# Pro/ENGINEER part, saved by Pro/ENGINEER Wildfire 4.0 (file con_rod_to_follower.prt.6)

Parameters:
  METRIC = "NO"

Other parameters: PITCH, DRILL_POINT_ANGLE, DRILL_DEPTH, DRILL_DIAMETER, THREAD_DIAMETER, THREADS_PER_INCH, THREAD_DEPTH, THREAD_LENGTH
